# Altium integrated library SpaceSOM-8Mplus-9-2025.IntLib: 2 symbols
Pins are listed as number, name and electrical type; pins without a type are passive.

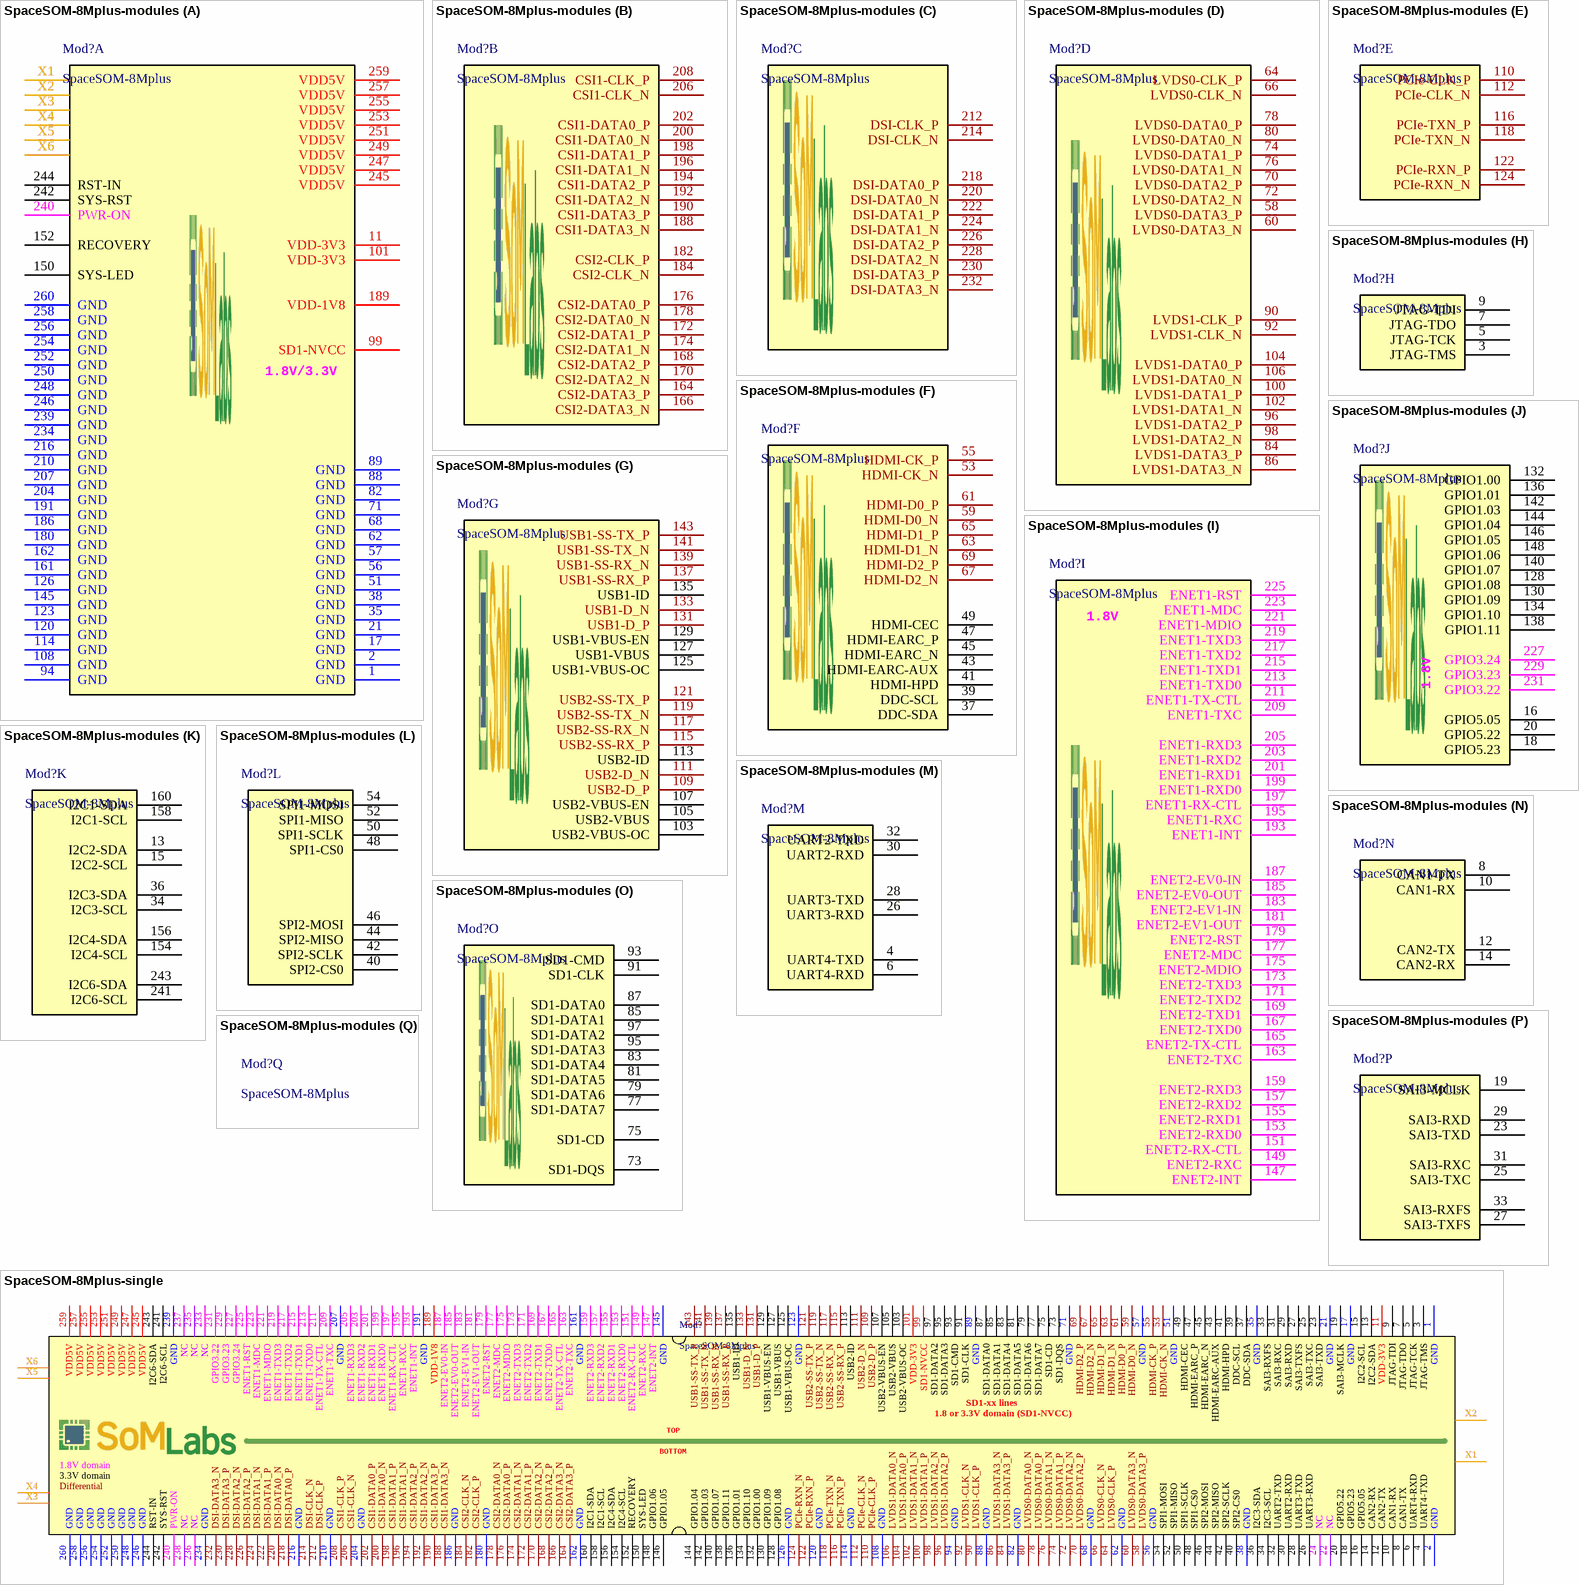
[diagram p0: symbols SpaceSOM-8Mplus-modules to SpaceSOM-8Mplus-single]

## SpaceSOM-8Mplus-modules
designator Mod?, comment SpaceSOM-8Mplus
SOM equipped with i.MX8M plus MPU; Manufacturer: SoMLabs
footprint SODIM260 (SODIM260 socket)
footprint SODIM260-SOM (SODIM260 socket + SoM)
footprint SODIM260-SOM-HEATSINK-FAN (SODIM260 socket + SoM + heatsink + fan)
footprint SODIMM260-SOM-large-heatsink (SODIM260 socket + SoM + heatsink SL-HEATSINK-85x40x10-A + fan YDM2006C05F)
footprint SODIMM260-SOM-large-heatsink-with-blower (SODIM260 socket + SoM + heatsink SL-HEATSINK-BLOWER-85x40x10-A + fan YDM2006C05F)
part A pins: 1 GND (power), 2 GND (power), 11 VDD-3V3 (power), 17 GND (power), 21 GND (power), 35 GND (power), 38 GND (power), 51 GND (power), 56 GND (power), 57 GND (power), 62 GND (power), 68 GND (power), 71 GND (power), 82 GND (power), 88 GND (power), 89 GND (power), 94 GND (power), 99 SD1-NVCC, 101 VDD-3V3 (power), 108 GND (power), 114 GND (power), 120 GND (power), 123 GND (power), 126 GND (power), 145 GND (power), 150 SYS-LED, 152 RECOVERY, 161 GND (power), 162 GND (power), 180 GND (power), 186 GND (power), 189 VDD-1V8 (power), 191 GND (power), 204 GND (power), 207 GND (power), 210 GND (power), 216 GND (power), 234 GND (power), 239 GND (power), 240 PWR-ON, 242 SYS-RST, 244 RST-IN, 245 VDD5V (power), 246 GND (power), 247 VDD5V (power), 248 GND (power), 249 VDD5V (power), 250 GND (power), 251 VDD5V (power), 252 GND (power), 253 VDD5V (power), 254 GND (power), 255 VDD5V (power), 256 GND (power), 257 VDD5V (power), 258 GND (power), 259 VDD5V (power), 260 GND (power), X1, X2, X3, X4, X5, X6
part B pins: 164 CSI2-DATA3_P, 166 CSI2-DATA3_N, 168 CSI2-DATA2_P, 170 CSI2-DATA2_N, 172 CSI2-DATA1_P, 174 CSI2-DATA1_N, 176 CSI2-DATA0_P, 178 CSI2-DATA0_N, 182 CSI2-CLK_P, 184 CSI2-CLK_N, 188 CSI1-DATA3_N, 190 CSI1-DATA3_P, 192 CSI1-DATA2_N, 194 CSI1-DATA2_P, 196 CSI1-DATA1_N, 198 CSI1-DATA1_P, 200 CSI1-DATA0_N, 202 CSI1-DATA0_P, 206 CSI1-CLK_N, 208 CSI1-CLK_P
part C pins: 212 DSI-CLK_P, 214 DSI-CLK_N, 218 DSI-DATA0_P, 220 DSI-DATA0_N, 222 DSI-DATA1_P, 224 DSI-DATA1_N, 226 DSI-DATA2_P, 228 DSI-DATA2_N, 230 DSI-DATA3_P, 232 DSI-DATA3_N
part D pins: 58 LVDS0-DATA3_P, 60 LVDS0-DATA3_N, 64 LVDS0-CLK_P, 66 LVDS0-CLK_N, 70 LVDS0-DATA2_P, 72 LVDS0-DATA2_N, 74 LVDS0-DATA1_P, 76 LVDS0-DATA1_N, 78 LVDS0-DATA0_P, 80 LVDS0-DATA0_N, 84 LVDS1-DATA3_P, 86 LVDS1-DATA3_N, 90 LVDS1-CLK_P, 92 LVDS1-CLK_N, 96 LVDS1-DATA2_P, 98 LVDS1-DATA2_N, 100 LVDS1-DATA1_P, 102 LVDS1-DATA1_N, 104 LVDS1-DATA0_P, 106 LVDS1-DATA0_N
part E pins: 110 PCIe-CLK_P, 112 PCIe-CLK_N, 116 PCIe-TXN_P, 118 PCIe-TXN_N, 122 PCIe-RXN_P, 124 PCIe-RXN_N
part F pins: 37 DDC-SDA, 39 DDC-SCL, 41 HDMI-HPD, 43 HDMI-EARC-AUX, 45 HDMI-EARC_N, 47 HDMI-EARC_P, 49 HDMI-CEC, 53 HDMI-CK_N, 55 HDMI-CK_P, 59 HDMI-D0_N, 61 HDMI-D0_P, 63 HDMI-D1_N, 65 HDMI-D1_P, 67 HDMI-D2_N, 69 HDMI-D2_P
part G pins: 103 USB2-VBUS-OC, 105 USB2-VBUS, 107 USB2-VBUS-EN, 109 USB2-D_P, 111 USB2-D_N, 113 USB2-ID, 115 USB2-SS-RX_P, 117 USB2-SS-RX_N, 119 USB2-SS-TX_N, 121 USB2-SS-TX_P, 125 USB1-VBUS-OC, 127 USB1-VBUS, 129 USB1-VBUS-EN, 131 USB1-D_P, 133 USB1-D_N, 135 USB1-ID, 137 USB1-SS-RX_P, 139 USB1-SS-RX_N, 141 USB1-SS-TX_N, 143 USB1-SS-TX_P
part H pins: 3 JTAG-TMS, 5 JTAG-TCK, 7 JTAG-TDO, 9 JTAG-TDI
part I pins: 147 ENET2-INT, 149 ENET2-RXC, 151 ENET2-RX-CTL, 153 ENET2-RXD0, 155 ENET2-RXD1, 157 ENET2-RXD2, 159 ENET2-RXD3, 163 ENET2-TXC, 165 ENET2-TX-CTL, 167 ENET2-TXD0, 169 ENET2-TXD1, 171 ENET2-TXD2, 173 ENET2-TXD3, 175 ENET2-MDIO, 177 ENET2-MDC, 179 ENET2-RST, 181 ENET2-EV1-OUT, 183 ENET2-EV1-IN, 185 ENET2-EV0-OUT, 187 ENET2-EV0-IN, 193 ENET1-INT, 195 ENET1-RXC, 197 ENET1-RX-CTL, 199 ENET1-RXD0, 201 ENET1-RXD1, 203 ENET1-RXD2, 205 ENET1-RXD3, 209 ENET1-TXC, 211 ENET1-TX-CTL, 213 ENET1-TXD0, 215 ENET1-TXD1, 217 ENET1-TXD2, 219 ENET1-TXD3, 221 ENET1-MDIO, 223 ENET1-MDC, 225 ENET1-RST
part J pins: 16 GPIO5.05, 18 GPIO5.23, 20 GPIO5.22, 128 GPIO1.08, 130 GPIO1.09, 132 GPIO1.00, 134 GPIO1.10, 136 GPIO1.01, 138 GPIO1.11, 140 GPIO1.07, 142 GPIO1.03, 144 GPIO1.04, 146 GPIO1.05, 148 GPIO1.06, 227 GPIO3.24, 229 GPIO3.23, 231 GPIO3.22
part K pins: 13 I2C2-SDA, 15 I2C2-SCL, 34 I2C3-SCL, 36 I2C3-SDA, 154 I2C4-SCL, 156 I2C4-SDA, 158 I2C1-SCL, 160 I2C1-SDA, 241 I2C6-SCL, 243 I2C6-SDA
part L pins: 40 SPI2-CS0, 42 SPI2-SCLK, 44 SPI2-MISO, 46 SPI2-MOSI, 48 SPI1-CS0, 50 SPI1-SCLK, 52 SPI1-MISO, 54 SPI1-MOSI
part M pins: 4 UART4-TXD, 6 UART4-RXD, 26 UART3-RXD, 28 UART3-TXD, 30 UART2-RXD, 32 UART2-TXD
part N pins: 8 CAN1-TX, 10 CAN1-RX, 12 CAN2-TX, 14 CAN2-RX
part O pins: 73 SD1-DQS, 75 SD1-CD, 77 SD1-DATA7, 79 SD1-DATA6, 81 SD1-DATA5, 83 SD1-DATA4, 85 SD1-DATA1, 87 SD1-DATA0, 91 SD1-CLK, 93 SD1-CMD, 95 SD1-DATA3, 97 SD1-DATA2
part P pins: 19 SAI3-MCLK, 23 SAI3-TXD, 25 SAI3-TXC, 27 SAI3-TXFS, 29 SAI3-RXD, 31 SAI3-RXC, 33 SAI3-RXFS

## SpaceSOM-8Mplus-single
designator Mod?, comment SpaceSOM-8Mplus
SOM equipped with i.MX8M plus MPU; Manufacturer: SoMLabs
footprint SODIM260 (SODIM260 socket)
footprint SODIM260-SOM (SODIM260 socket + SoM)
footprint SODIM260-SOM-HEATSINK-FAN (SODIM260 socket + SoM + heatsink + fan)
pins: 1 GND (power), 2 GND (power), 3 JTAG-TMS, 4 UART4-TXD, 5 JTAG-TCK, 6 UART4-RXD, 7 JTAG-TDO, 8 CAN1-TX, 9 JTAG-TDI, 10 CAN1-RX, 11 VDD-3V3 (power), 12 CAN2-TX, 13 I2C2-SDA, 14 CAN2-RX, 15 I2C2-SCL, 16 GPIO5.05, 17 GND (power), 18 GPIO5.23, 19 SAI3-MCLK, 20 GPIO5.22, 21 GND (power), 22 NC, 23 SAI3-TXD, 24 NC, 25 SAI3-TXC, 26 UART3-RXD, 27 SAI3-TXFS, 28 UART3-TXD, 29 SAI3-RXD, 30 UART2-RXD, 31 SAI3-RXC, 32 UART2-TXD, 33 SAI3-RXFS, 34 I2C3-SCL, 35 GND (power), 36 I2C3-SDA, 37 DDC-SDA, 38 GND (power), 39 DDC-SCL, 40 SPI2-CS0, 41 HDMI-HPD, 42 SPI2-SCLK, 43 HDMI-EARC-AUX, 44 SPI2-MISO, 45 HDMI-EARC_N, 46 SPI2-MOSI, 47 HDMI-EARC_P, 48 SPI1-CS0, 49 HDMI-CEC, 50 SPI1-SCLK, 51 GND (power), 52 SPI1-MISO, 53 HDMI-CK_N, 54 SPI1-MOSI, 55 HDMI-CK_P, 56 GND (power), 57 GND (power), 58 LVDS0-DATA3_P, 59 HDMI-D0_N, 60 LVDS0-DATA3_N, 61 HDMI-D0_P, 62 GND (power), 63 HDMI-D1_N, 64 LVDS0-CLK_P, 65 HDMI-D1_P, 66 LVDS0-CLK_N, 67 HDMI-D2_N, 68 GND (power), 69 HDMI-D2_P, 70 LVDS0-DATA2_P, 71 GND (power), 72 LVDS0-DATA2_N, 73 SD1-DQS, 74 LVDS0-DATA1_P, 75 SD1-CD, 76 LVDS0-DATA1_N, 77 SD1-DATA7, 78 LVDS0-DATA0_P, 79 SD1-DATA6, 80 LVDS0-DATA0_N, 81 SD1-DATA5, 82 GND (power), 83 SD1-DATA4, 84 LVDS1-DATA3_P, 85 SD1-DATA1, 86 LVDS1-DATA3_N, 87 SD1-DATA0, 88 GND (power), 89 GND (power), 90 LVDS1-CLK_P, 91 SD1-CLK, 92 LVDS1-CLK_N, 93 SD1-CMD, 94 GND (power), 95 SD1-DATA3, 96 LVDS1-DATA2_P, 97 SD1-DATA2, 98 LVDS1-DATA2_N, 99 SD1-NVCC, 100 LVDS1-DATA1_P, 101 VDD-3V3 (power), 102 LVDS1-DATA1_N, 103 USB2-VBUS-OC, 104 LVDS1-DATA0_P, 105 USB2-VBUS, 106 LVDS1-DATA0_N, 107 USB2-VBUS-EN, 108 GND (power), 109 USB2-D_P, 110 PCIe-CLK_P, 111 USB2-D_N, 112 PCIe-CLK_N, 113 USB2-ID, 114 GND (power), 115 USB2-SS-RX_P, 116 PCIe-TXN_P, 117 USB2-SS-RX_N, 118 PCIe-TXN_N, 119 USB2-SS-TX_N, 120 GND (power), 121 USB2-SS-TX_P, 122 PCIe-RXN_P, 123 GND (power), 124 PCIe-RXN_N, 125 USB1-VBUS-OC, 126 GND (power), 127 USB1-VBUS, 128 GPIO1.08, 129 USB1-VBUS-EN, 130 GPIO1.09, 131 USB1-D_P, 132 GPIO1.00, 133 USB1-D_N, 134 GPIO1.10, 135 USB1-ID, 136 GPIO1.01, 137 USB1-SS-RX_P, 138 GPIO1.11, 139 USB1-SS-RX_N, 140 GPIO1.07, 141 USB1-SS-TX_N, 142 GPIO1.03, 143 USB1-SS-TX_P, 144 GPIO1.04, 145 GND (power), 146 GPIO1.05, 147 ENET2-INT, 148 GPIO1.06, 149 ENET2-RXC, 150 SYS-LED, 151 ENET2-RX-CTL, 152 RECOVERY, 153 ENET2-RXD0, 154 I2C4-SCL, 155 ENET2-RXD1, 156 I2C4-SDA, 157 ENET2-RXD2, 158 I2C1-SCL, 159 ENET2-RXD3, 160 I2C1-SDA, 161 GND (power), 162 GND (power), 163 ENET2-TXC, 164 CSI2-DATA3_P, 165 ENET2-TX-CTL, 166 CSI2-DATA3_N, 167 ENET2-TXD0, 168 CSI2-DATA2_P, 169 ENET2-TXD1, 170 CSI2-DATA2_N, 171 ENET2-TXD2, 172 CSI2-DATA1_P, 173 ENET2-TXD3, 174 CSI2-DATA1_N, 175 ENET2-MDIO, 176 CSI2-DATA0_P, 177 ENET2-MDC, 178 CSI2-DATA0_N, 179 ENET2-RST, 180 GND (power), 181 ENET2-EV1-OUT, 182 CSI2-CLK_P, 183 ENET2-EV1-IN, 184 CSI2-CLK_N, 185 ENET2-EV0-OUT, 186 GND (power), 187 ENET2-EV0-IN, 188 CSI1-DATA3_N, 189 VDD-1V8 (power), 190 CSI1-DATA3_P, 191 GND (power), 192 CSI1-DATA2_N, 193 ENET1-INT, 194 CSI1-DATA2_P, 195 ENET1-RXC, 196 CSI1-DATA1_N, 197 ENET1-RX-CTL, 198 CSI1-DATA1_P, 199 ENET1-RXD0, 200 CSI1-DATA0_N, 201 ENET1-RXD1, 202 CSI1-DATA0_P, 203 ENET1-RXD2, 204 GND (power), 205 ENET1-RXD3, 206 CSI1-CLK_N, 207 GND (power), 208 CSI1-CLK_P, 209 ENET1-TXC, 210 GND (power), 211 ENET1-TX-CTL, 212 DSI-CLK_P, 213 ENET1-TXD0, 214 DSI-CLK_N, 215 ENET1-TXD1, 216 GND (power), 217 ENET1-TXD2, 218 DSI-DATA0_P, 219 ENET1-TXD3, 220 DSI-DATA0_N, 221 ENET1-MDIO, 222 DSI-DATA1_P, 223 ENET1-MDC, 224 DSI-DATA1_N, 225 ENET1-RST, 226 DSI-DATA2_P, 227 GPIO3.24, 228 DSI-DATA2_N, 229 GPIO3.23, 230 DSI-DATA3_P, 231 GPIO3.22, 232 DSI-DATA3_N, 233 NC, 234 GND (power), 235 NC, 236 NC, 237 NC, 238 NC, 239 GND (power), 240 PWR-ON, 241 I2C6-SCL, 242 SYS-RST, 243 I2C6-SDA, 244 RST-IN, 245 VDD5V (power), 246 GND (power), 247 VDD5V (power), 248 GND (power), 249 VDD5V (power), 250 GND (power), 251 VDD5V (power), 252 GND (power), 253 VDD5V (power), 254 GND (power), 255 VDD5V (power), 256 GND (power), 257 VDD5V (power), 258 GND (power), 259 VDD5V (power), 260 GND (power), X1, X2, X3, X4, X5, X6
